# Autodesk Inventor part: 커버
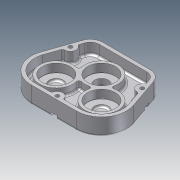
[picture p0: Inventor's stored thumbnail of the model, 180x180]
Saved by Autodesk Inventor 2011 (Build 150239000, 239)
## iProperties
Company: 한국ATC센터
Created: 2014-12
Part Number: 커버
Document SubType Name: Modeling
Designer: KYOUNG IL JANG
Density: 1 g/cm^3
Mass: 160.364 g
Surface Area: 512.085 cm^2
Volume: 160.364 cm^3
Author: KYOUNG IL JANG
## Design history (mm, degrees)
sketch "스케치1"
  geometry: L1 (-66.565, -20.803)-(-47, 36); L2 (47, 36)-(66.565, -20.803); L3 (-32.527, -68.527)-(32.527, -68.527); L4 (-47, 36)-(47, 36); C1 r 28 at (0, 0); C2 r 18 at (-32.527, -32.527); C3 r 18 at (32.527, -32.527); A1 r 36 centre (-32.527, -32.527) between (-66.565, -20.803) and (-32.527, -68.527); A2 r 36 centre (32.527, -32.527) between (32.527, -68.527) and (66.565, -20.803); 2 further points
  constraints: 8 end point, 6 tangent, 5 centre point, 4 point on circle, 3 coincident, 2 equal radius, 1 equal length, 1 horizontal alignment, 1 midpoint, 1 vertical alignment
  dimensions: "d0" = 56 diameter of C1; "d1" = 36 diameter of C2; "d2" = 90 deg dimension on point (0, 0) C3.centre C2.centre; "d3" = 36 radius of A1; "d4" = 104.52691 distance between parallel lines of L3 L4 (derived); "d5" = 94 distance of L1.end L2.start; "d65" = 36 distance from line of point (0, 0) L4
extrude "돌출1" new body sketch "스케치1" distance "d6" = 25; taper "d7" = 0 deg
fillet "모깎기1" dims "d8" = 18
feature "쉘1" dims "d9" = 9, "d10" = 5
sketch "스케치2"
  geometry: C1 r 24 at (1.635, -63.527); C2 r 24 at (66.689, -63.527); C3 r 24 at (34.162, -31); 4 further points
  constraints: 4 coincident, 3 centre point, 1 equal radius
  dimensions: "d11" = 48 diameter of C3; "d12" = 48 diameter of C2
extrude "돌출2" join sketch "스케치2" distance "d13" = 11; taper "d14" = 0 deg
hole "구멍1" diameter "d17" = 20; stored, may be unused: countersink angle "d21" = 90 deg, drill point angle "d23" = 0 deg; dims "d15" = 10, "d16" = 10, "d18" = 6, "d19" = 40, "d20" = 12, "d22" = 3
hole "구멍2" diameter "d26" = 20; stored, may be unused: countersink angle "d30" = 90 deg, drill point angle "d32" = 0 deg; dims "d24" = 10, "d25" = 10, "d27" = 6, "d28" = 40, "d29" = 12, "d31" = 3
hole "구멍3" diameter "d35" = 20; stored, may be unused: countersink angle "d39" = 90 deg, drill point angle "d41" = 118 deg; dims "d33" = 10, "d34" = 10, "d36" = 6, "d37" = 40, "d38" = 12, "d40" = 3
sketch "스케치3"
  geometry: C1 r 15 at (0, 0); C2 r 20 at (0, 0); 1 further point
  constraints: 2 centre point, 2 coincident
  dimensions: "d42" = 40 diameter of C2; "d43" = 30 diameter of C1
extrude "돌출3" join sketch "스케치3" distance "d44" = 8; taper "d45" = 0 deg
feature "면 기울기1" dims angle "d46" = 10 deg
fillet "모깎기2" dims "d47" = 3
fillet "모깎기3" dims "d48" = 0.3
fillet "모깎기6" dims "d66" = 0.1
sketch "스케치4"
  geometry: L1 (-61.837, -22.432)-(-46.453, 22.233) reference; L2 (46.453, 22.233)-(61.837, -22.432) reference; L3 (32.527, -63.527)-(-32.527, -63.527) reference; L4 (-34.162, 31)-(34.162, 31) reference; A1 r 8 centre (51.7, 7) between (49.095, 14.564) and (54.305, -0.564); A2 r 8 centre (-51.7, 7) between (-54.305, -0.564) and (-49.095, 14.564); A3 r 8 centre (0, -63.527) between (8, -63.527) and (-8, -63.527)
  constraints: 8 point on line, 6 point on circle, 3 centre point, 2 equal radius, 1 horizontal alignment, 1 midpoint
  dimensions: "d49" = 8 radius of A1; "d51" = 24 distance from line of A2.centre L4
extrude "돌출4" join sketch "스케치4" stored distance "d52" = 8; taper "d53" = 0 deg
fillet "모깎기4" dims "d54" = 3
sketch "스케치5"
  geometry: A1 r 8 centre (-51.7, 7) between (-52.144, -0.988) and (-47.131, 13.567) reference; A2 r 8 centre (0, -63.527) between (7.697, -61.345) and (-7.697, -61.345) reference; A3 r 8 centre (51.7, 7) between (47.131, 13.567) and (52.144, -0.988) reference; 1 further point
hole "구멍4" sketch "스케치5" at (0, -63.527), (-51.7, 7), (51.7, 7) diameter "d55" = 5.5; stored, may be unused: countersink angle "d59" = 90 deg, drill point angle "d61" = 118 deg; dims "d56" = 6, "d57" = 9.5, "d58" = 5.4, "d60" = 3
sketch "스케치6"
  geometry: L1 (-51.181, 23.862)-(-66.565, -20.803) reference; L2 (66.565, -20.803)-(51.181, 23.862) reference; L3 (-32.527, -68.527)-(32.527, -68.527) reference; L4 (-50.153, 11.491)-(-54.881, 13.119); L5 (-53.247, 2.509)-(-57.974, 4.137); L6 (50.153, 11.491)-(54.881, 13.119); L7 (53.247, 2.509)-(57.974, 4.137); L8 (4.75, -63.527)-(4.75, -68.527); L9 (-4.75, -63.527)-(-4.75, -68.527); A1 r 4.75 centre (-51.7, 7) between (-54.994, 3.578) and (-52.188, 11.725) reference; A2 r 4.75 centre (51.7, 7) between (52.188, 11.725) and (54.994, 3.578) reference; A3 r 4.75 centre (0, -63.527) between (4.308, -65.527) and (-4.308, -65.527) reference; 1 further point
  constraints: 12 end point, 6 perpendicular, 6 point on circle, 6 point on line, 6 tangent
extrude "돌출5" cut sketch "스케치6" distance "d62" = 5.4; taper "d63" = 0 deg
fillet "모깎기5" dims "d64" = 3
node "솔리드1"
